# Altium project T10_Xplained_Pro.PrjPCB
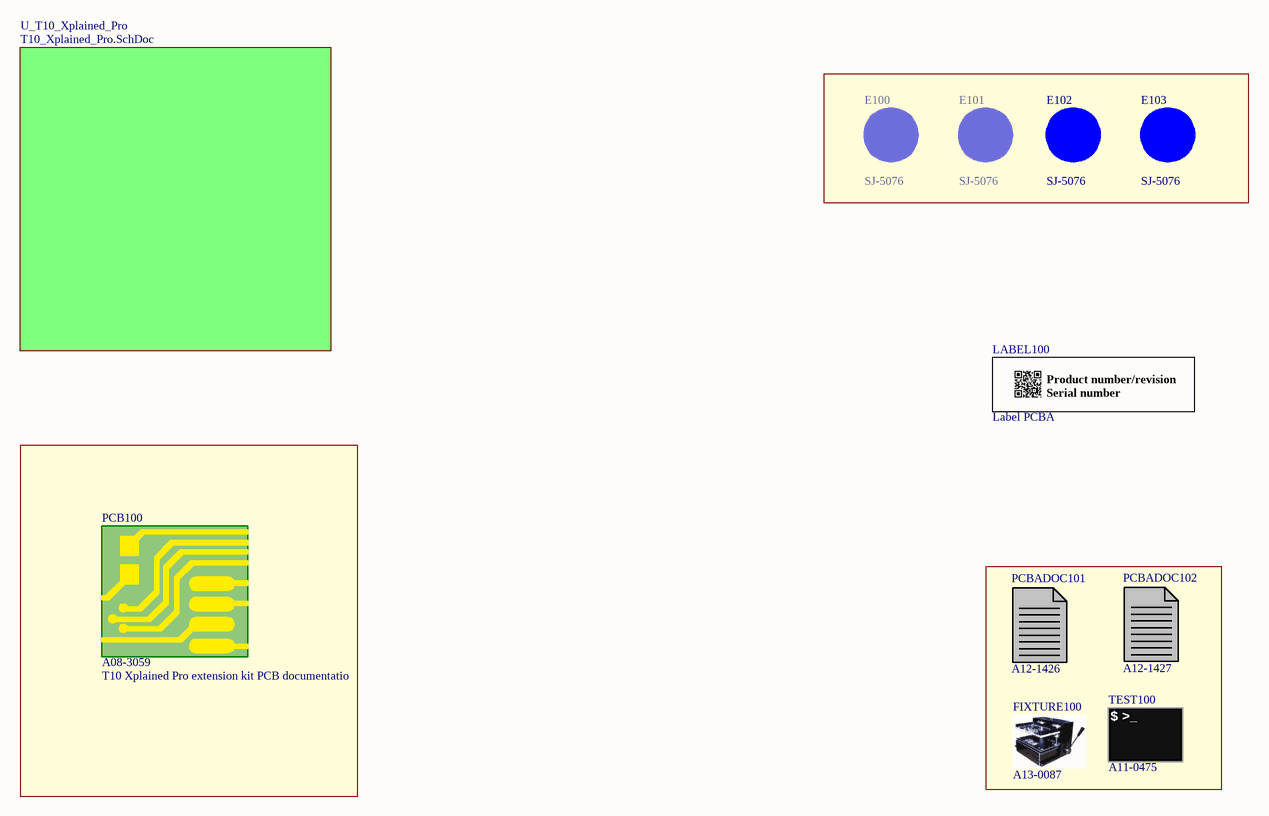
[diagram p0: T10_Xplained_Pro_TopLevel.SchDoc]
2 sheets, 68 parts. Net scope: global (net labels, ports and power ports of the same name join across sheets).
Board file: T10_Xplained_Pro.PcbDoc
Sheets:
  T10_Xplained_Pro_TopLevel.SchDoc
    U_T10_Xplained_Pro = T10_Xplained_Pro.SchDoc

## Sheet T10_Xplained_Pro_TopLevel.SchDoc: Top Level
size A3; Organization: ATMEL Norway; Address1: Vestre Rosten 79; Address2: N-7075 TILLER; Address3: NORWAY; DocumentNumber: A09-3338; Revision: 1; SheetNumber: 1; SheetTotal: 2; DrawnBy: Sivaram SL; Engineer: Sivaram SL; PageSetup: Record=PageOptions¦CenterHorizontal=True¦CenterVertical=True¦PrintScale=1.01¦XCorrection=1.00¦YCorrection=1.00¦PrintKind=1¦BorderSize=5000000¦LeftOffset=0¦BottomOffset=0¦Orientation=2¦PaperLength=1000¦PaperWidth=1000¦Scale=100¦PaperSource=7¦PrintQuality=-4¦MediaType=1¦DitherType=10¦PaperKind=Letter¦PrintScaleMode=1

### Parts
?  (no value)  (graphical)
E100  value SJ-5076  [AP8-00192]
E101  value SJ-5076  [AP8-00192]
E102  value SJ-5076  [AP8-00192]
E103  value SJ-5076  [AP8-00192]
FIXTURE100  AN: A13-0087  (hidden comment: JIG)  (mechanical)
LABEL100  value Label PCBA  [AP8-00317]
PCB100  value T10 Xplained Pro extension kit PCB documentatio  AN: A08-3059  (hidden comment: PCB)  (mechanical)
PCBADOC101  AN: A12-1426  (hidden comment: PCBADOC)  (mechanical)
PCBADOC102  AN: A12-1427  (hidden comment: PCBADOC)  (mechanical)
TEST100  AN: A11-0475  (hidden comment: TEST)  (mechanical)

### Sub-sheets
U_T10_Xplained_Pro = T10_Xplained_Pro.SchDoc: no entries

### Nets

Not connected (* = marked no-connect by the designer): E100 1(FIDUCIAL); E101 1(FIDUCIAL); E102 1(FIDUCIAL); E103 1(FIDUCIAL)

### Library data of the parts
? = Title Block A3
E100-E103 = A08-0053: 2.8mm adhesive feet,diam 8.0mm; PartGroup: Mechanical devices,Mounting accessories; Manufacturer: 3M
FIXTURE100 = A13-0087: Xplained PRO Extension board Jupiter Test Fixture; PartGroup: Test Equipment,Test Fixtures; Manufacturer: ESCATEC
LABEL100 = A09-0611: PCBA identification label PP Top White Gloss; PartGroup: Mechanical devices,Packaging materials,Printed Labels; Manufacturer: ACT Logimark AS; MPN: 505462
PCB100 = A08-3059: T10 Xplained Pro extension kit PCB documentation; PartGroup: Mechanical devices,Printed circuit boards; ComponentStatus: 'Active (verified)'
PCBADOC101 = A12-1426: T10 Xplained Pro extension kit PCBA Documentation; PartGroup: Documentation,PCBA Documents,Atmel; ComponentStatus: 'New (not verified)'
PCBADOC102 = A12-1427: T10 Xplained Pro Test Documentation; PartGroup: Documentation,Procedures,Test Instructions; ComponentStatus: 'New (not verified)'
TEST100 = A11-0475: Fixture eggTest for T10 Xplained Pro; PartGroup: Software,Test software,Starter Kit; Value: T10 Xplained Pro test software; ComponentStatus: 'New (not verified)'

## Sheet T10_Xplained_Pro.SchDoc: T10-Xplained Pro
size A3; Organization: ATMEL Norway; Address1: Vestre Rosten 79; Address2: N-7075 TILLER; Address3: NORWAY; DocumentNumber: A09-3338; Revision: 1; SheetNumber: 2; SheetTotal: 2; DrawnBy: Sivaram SL; Engineer: Sivaram SL; PageSetup: Record=PageOptions¦CenterHorizontal=True¦CenterVertical=True¦PrintScale=1.01¦XCorrection=1.00¦YCorrection=1.00¦PrintKind=1¦BorderSize=5000000¦LeftOffset=0¦BottomOffset=0¦Orientation=2¦PaperLength=1000¦PaperWidth=1000¦Scale=100¦PaperSource=7¦PrintQuality=-4¦MediaType=1¦DitherType=10¦PaperKind=A3 (297 x 420 mm)¦PrintScaleMode=1
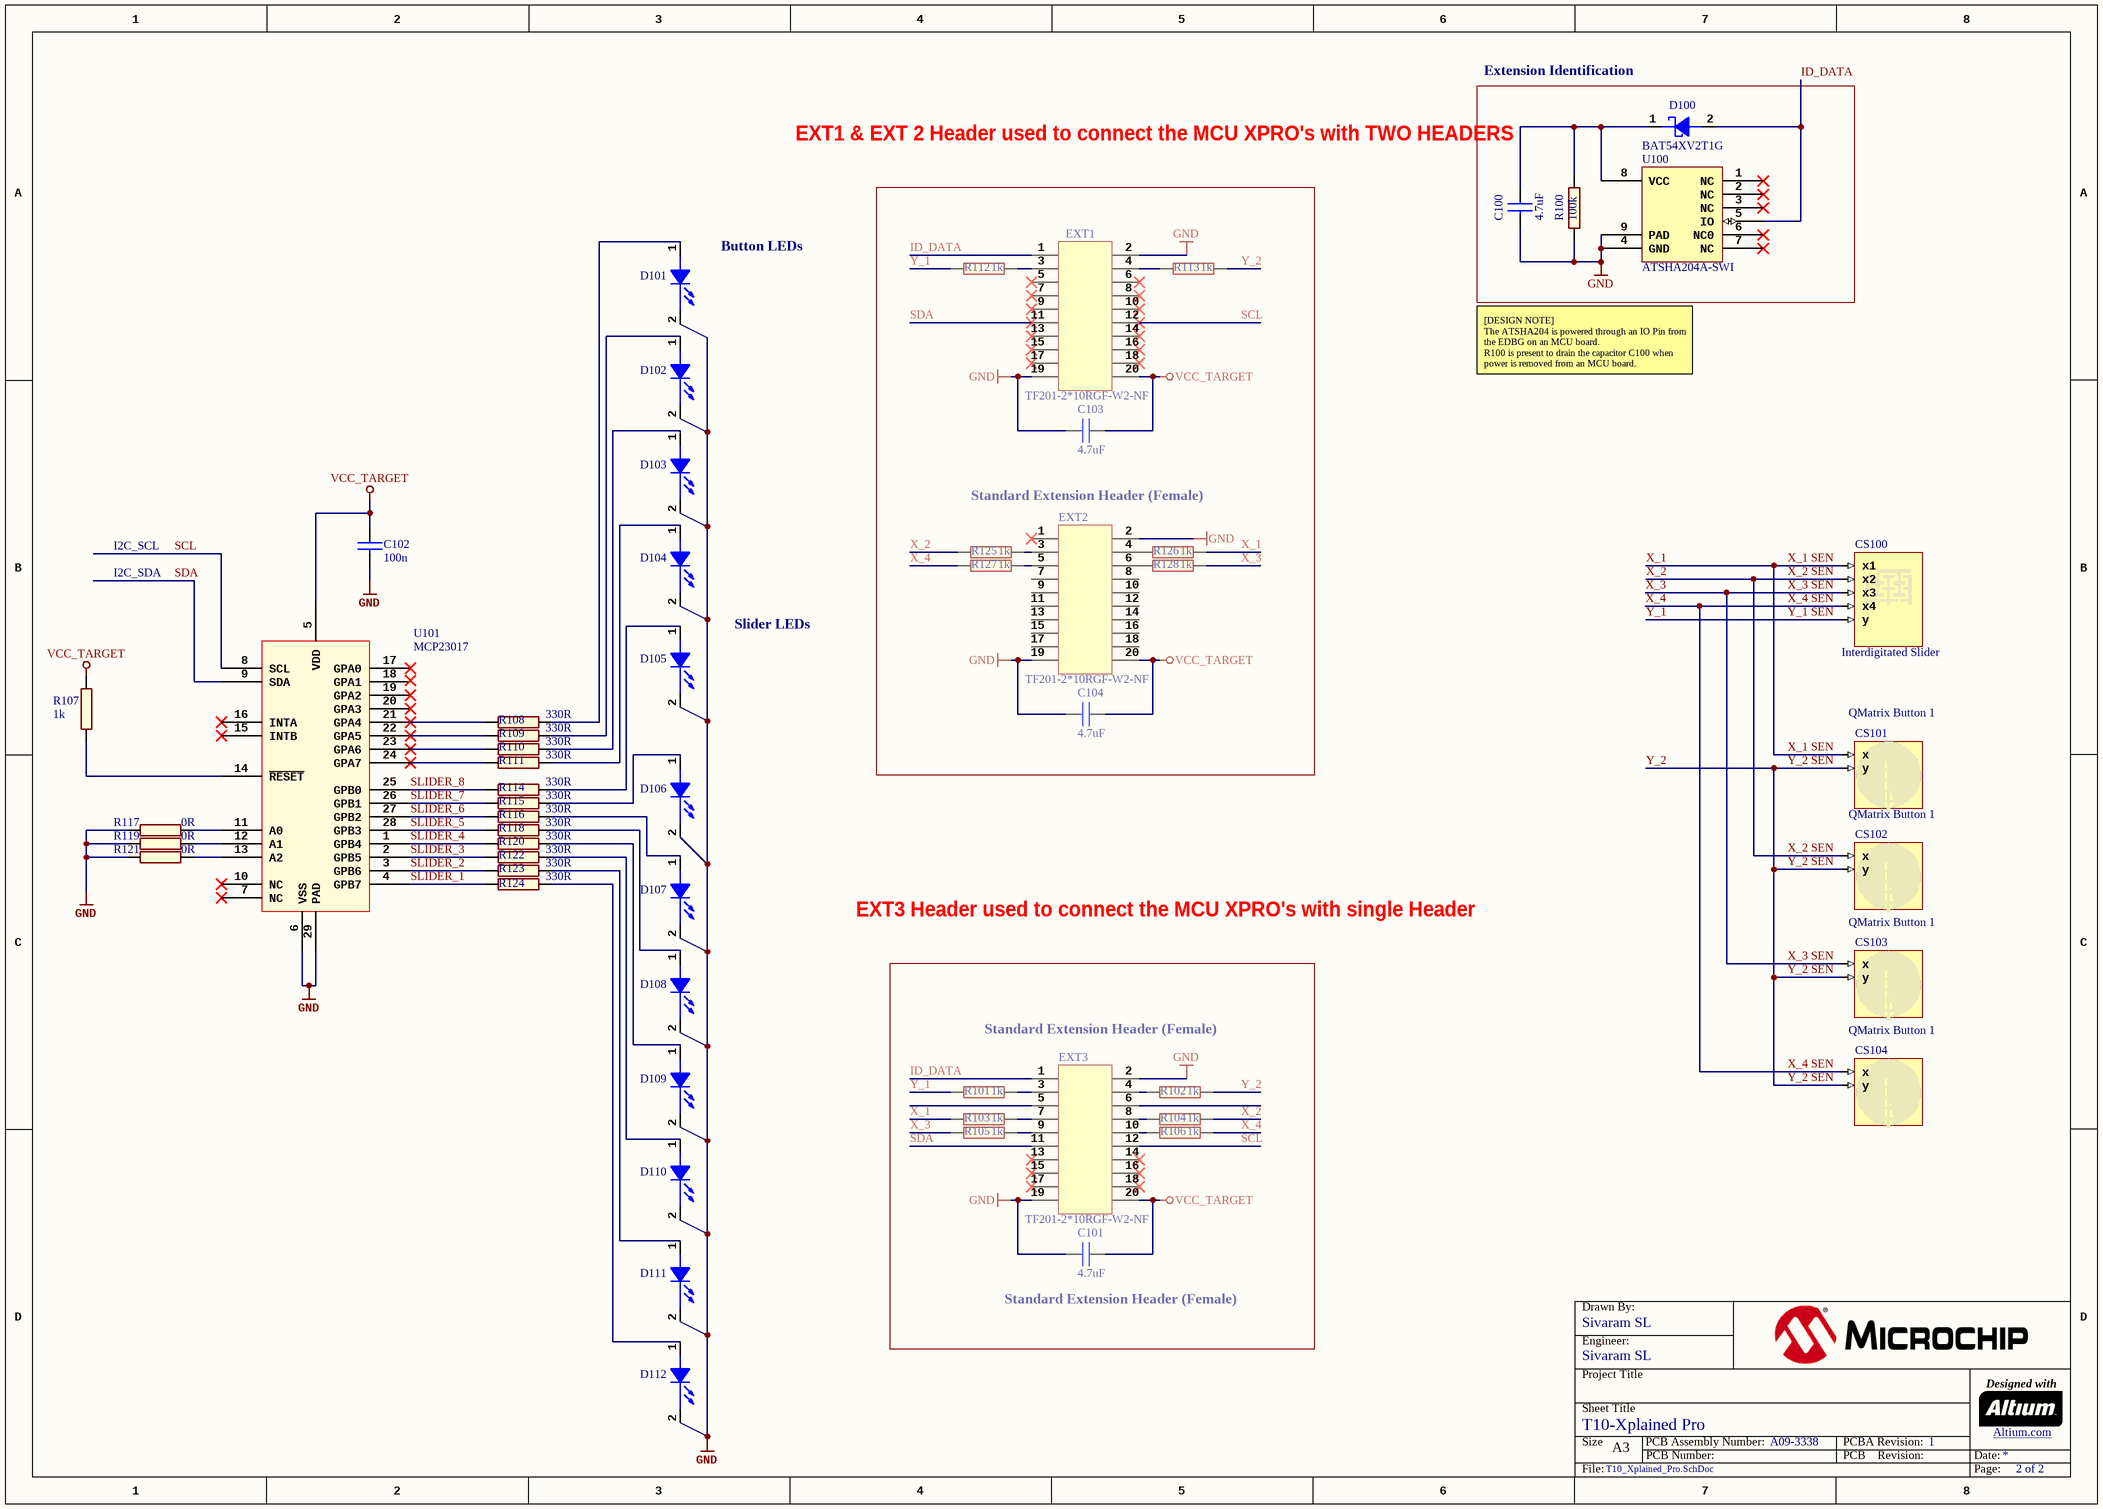
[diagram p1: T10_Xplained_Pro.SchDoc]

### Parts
C100  value 4.7uF  [AP1-00001]  (hidden comment: Recommended by Escatec. No datasheet available yet.)
C101  value 4.7uF  [AP1-00001]
C102  value 100n  [AP1-00053]
C103  value 4.7uF  [AP1-00001]
C104  value 4.7uF  [AP1-00001]
CS100  Interdigitated Slider  (no BOM)
CS101  QMatrix Button 1  (no BOM)
CS102  QMatrix Button 1  (no BOM)
CS103  QMatrix Button 1  (no BOM)
CS104  QMatrix Button 1  (no BOM)
D100  value BAT54XV2T1G  [AP4-00036]  (hidden comment: Farnell# 1615809)
D101  LED_21  [AP4-00115]  (value not drawn)
D102  LED_21  [AP4-00115]  (value not drawn)
D103  LED_21  [AP4-00115]  (value not drawn)
D104  LED_21  [AP4-00115]  (value not drawn)
D105  LED_21  [AP4-00115]  (value not drawn)
D106  LED_21  [AP4-00115]  (value not drawn)
D107  LED_21  [AP4-00115]  (value not drawn)
D108  LED_21  [AP4-00115]  (value not drawn)
D109  LED_21  [AP4-00115]  (value not drawn)
D110  LED_21  [AP4-00115]  (value not drawn)
D111  LED_21  [AP4-00115]  (value not drawn)
D112  LED_21  [AP4-00115]  (value not drawn)
EXT1  value TF201-2*10RGF-W2-NF  [AP8-00621]
EXT2  value TF201-2*10RGF-W2-NF  [AP8-00621]
EXT3  value TF201-2*10RGF-W2-NF  [AP8-00621]
R100  value 100k  [AP2-00000]  (hidden comment: R2)
R101  value 1k  [AP2-00000]  (hidden comment: R2)
R102  value 1k  [AP2-00000]  (hidden comment: R2)
R103  value 1k  [AP2-00000]  (hidden comment: R2)
R104  value 1k  [AP2-00000]  (hidden comment: R2)
R105  value 1k  [AP2-00000]  (hidden comment: R2)
R106  value 1k  [AP2-00000]  (hidden comment: R2)
R107  value 1k  [AP2-00011]
R108  value 330R  [AP2-00000]  (hidden comment: R2)
R109  value 330R  [AP2-00000]  (hidden comment: R2)
R110  value 330R  [AP2-00000]  (hidden comment: R2)
R111  value 330R  [AP2-00000]  (hidden comment: R2)
R112  value 1k  [AP2-00000]  (hidden comment: R2)
R113  value 1k  [AP2-00000]  (hidden comment: R2)
R114  value 330R  [AP2-00000]  (hidden comment: R2)
R115  value 330R  [AP2-00000]  (hidden comment: R2)
R116  value 330R  [AP2-00000]  (hidden comment: R2)
R117  value 0R  [AP2-00000]  (hidden comment: R2)
R118  value 330R  [AP2-00000]  (hidden comment: R2)
R119  value 0R  [AP2-00000]  (hidden comment: R2)
R120  value 330R  [AP2-00000]  (hidden comment: R2)
R121  value 0R  [AP2-00000]  (hidden comment: R2)
R122  value 330R  [AP2-00000]  (hidden comment: R2)
R123  value 330R  [AP2-00000]  (hidden comment: R2)
R124  value 330R  [AP2-00000]  (hidden comment: R2)
R125  value 1k  [AP2-00000]  (hidden comment: R2)
R126  value 1k  [AP2-00000]  (hidden comment: R2)
R127  value 1k  [AP2-00000]  (hidden comment: R2)
R128  value 1k  [AP2-00000]  (hidden comment: R2)
U100  ATSHA204A-SWI  [AP6-00409]
U101  value MCP23017  [AP6-00497]  (hidden comment: MCP23017-E_ML)

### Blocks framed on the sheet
Extension Identification: C100 D100 R100 U100
Standard Extension Header (Female): C103 C104 EXT1 EXT2 R112 R113 R125-R128

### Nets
GND: C100.2 C101.2 C102.2 C103.2 C104.2 D101.2(CATHODE) D102.2(CATHODE) D103.2(CATHODE) D104.2(CATHODE) D105.2(CATHODE) D106.2(CATHODE) D107.2(CATHODE) D108.2(CATHODE) D109.2(CATHODE) D110.2(CATHODE) D111.2(CATHODE) D112.2(CATHODE) EXT1.2 EXT1.19 EXT2.2 EXT2.19 EXT3.2 EXT3.19 R100.1 R117.1 R119.1 R121.1 U100.4(GND) U100.9(PAD) U101.6(VSS) U101.29(PAD)
VCC_TARGET: C101.1 C102.1 C103.1 C104.1 EXT1.20 EXT2.20 EXT3.20 R107.2 U101.5(VDD)
ID_DATA: D100.2(ANODE) EXT1.1 EXT3.1 U100.5(IO)
SCL: EXT1.12 EXT3.12 U101.8(SCL)
SDA: EXT1.11 EXT3.11 U101.9(SDA)
SLIDER_1: R124.1 U101.4(GPB7)
SLIDER_2: R123.1 U101.3(GPB6)
SLIDER_3: R122.1 U101.2(GPB5)
SLIDER_4: R120.1 U101.1(GPB4)
SLIDER_5: R118.1 U101.28(GPB3)
SLIDER_6: R116.1 U101.27(GPB2)
SLIDER_7: R115.1 U101.26(GPB1)
SLIDER_8: R114.1 U101.25(GPB0)
X_1: CS100.x1 CS101.x R103.2 R126.1  [also labelled X_1 SEN]
X_2: CS100.x2 CS102.x R104.1 R125.2  [also labelled X_2 SEN]
X_3: CS100.x3 CS103.x R105.2 R128.1  [also labelled X_3 SEN]
X_4: CS100.x4 CS104.x R106.1 R127.2  [also labelled X_4 SEN]
Y_1: CS100.y R101.2 R112.2  [also labelled Y_1 SEN]
Y_2: CS101.y CS102.y CS103.y CS104.y R102.1 R113.1  [also labelled Y_2 SEN]
NetC100_1: C100.1 D100.1(CATHODE) R100.2 U100.8(VCC)
NetD101_1: D101.1(ANODE) R108.2
NetD102_1: D102.1(ANODE) R109.2
NetD103_1: D103.1(ANODE) R110.2
NetD104_1: D104.1(ANODE) R111.2
NetD105_1: D105.1(ANODE) R114.2
NetD106_1: D106.1(ANODE) R115.2
NetD107_1: D107.1(ANODE) R116.2
NetD108_1: D108.1(ANODE) R118.2
NetD109_1: D109.1(ANODE) R120.2
NetD110_1: D110.1(ANODE) R122.2
NetD111_1: D111.1(ANODE) R123.2
NetD112_1: D112.1(ANODE) R124.2
NetEXT1_3: EXT1.3 R112.1
NetEXT1_4: EXT1.4 R113.2
NetEXT2_3: EXT2.3 R125.1
NetEXT2_4: EXT2.4 R126.2
NetEXT2_5: EXT2.5 R127.1
NetEXT2_6: EXT2.6 R128.2
NetEXT3_3: EXT3.3 R101.1
NetEXT3_4: EXT3.4 R102.2
NetEXT3_7: EXT3.7 R103.1
NetEXT3_8: EXT3.8 R104.2
NetEXT3_9: EXT3.9 R105.1
NetEXT3_10: EXT3.10 R106.2
NetR107_1: R107.1 U101.14(~{RESET})
NetR108_1: R108.1 U101.21(GPA4)
NetR109_1: R109.1 U101.22(GPA5)
NetR110_1: R110.1 U101.23(GPA6)
NetR111_1: R111.1 U101.24(GPA7)
NetR117_2: R117.2 U101.11(A0)
NetR119_2: R119.2 U101.12(A1)
NetR121_2: R121.2 U101.13(A2)

Not connected (* = marked no-connect by the designer): EXT1 5* 6* 7* 8* 9* 10* 13* 14* 15* 16* 17* 18*; EXT2 1* 7 8 9 10 11 12 13 14 15 16 17 18; EXT3 5 6 13* 14* 15* 16* 17* 18*; U100 1(NC)* 2(NC)* 3(NC)* 6(NC0)* 7(NC)*; U101 7(NC)* 10(NC)* 15(INTB)* 16(INTA)* 17(GPA0)* 18(GPA1) 19(GPA2)* 20(GPA3)*

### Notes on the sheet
- EXT1 & EXT 2 Header used to connect the MCU XPRO's with TWO HEADERS
- (near D101) Button LEDs
- [DESIGN NOTE]
  The ATSHA204 is powered through an IO Pin from the EDBG on an MCU board.
  R100 is present to drain the capacitor C100 when power is removed from an MCU board.
- I2C_SCL
- I2C_SDA
- Slider LEDs
- EXT3 Header used to connect the MCU XPRO's with single Header
- Standard Extension Header (Female)
- (near C101) Standard Extension Header (Female)

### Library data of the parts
C100 = A01-0347: Ceramic capacitor, SMD 0402, X5R, 6.3V, +/-20% (de33687); PartGroup: Capacitors,Ceramic,SMD 0402; Manufacturer: Murata; MPN: GRM155R60J475ME87D; Tolerance: +-20%; TemperatureRange: -55°C to +85°C; ComponentStatus: 'Active (verified)'
C101 C103 C104 = A01-0347: Ceramic capacitor, SMD 0402, X5R, 6.3V, +/-20% (de33687); PartGroup: Capacitors,Ceramic,SMD 0402; Manufacturer: Murata; MPN: GRM155R60J475ME87D; Tolerance: +-20%; TemperatureRange: -55°C to +85°C
C102 = A01-0246: Ceramic capacitor, SMD 0402, X7R, 16V, +/-10%; PartGroup: Capacitors,Ceramic,SMD 0402; Manufacturer: Kemet; MPN: C0402C104K4RACTU; TemperatureRange: -55 - +125 deg C; ComponentStatus: 'Active (verified)'
CS100 = InterdigitatedSlider: Interdigitated Matrix Slider; ConfiguratorName: ATMEL_TOUCH; ConfigurationParameters: {}__sensorid[10]{}segmentWidth[12]{}height[10]{}yThickness[0.5]{}xThickness[0.5]{}gapThickness[0.5]{}channels[4]{}
CS101-CS104 = QMatrixButton: QMatrix Button; ConfiguratorName: ATMEL_TOUCH; ConfigurationParameters: {}__sensorid[3]{}width[10]{}height[10]{}yThickness[0.5]{}xThickness[0.5]{}gapThickness[0.5]{}path[1]{}
D100 = A04-0049: Schottky diode, If:200mA, Vf:0.35V, Vrrm:30V, SOD-523; PartGroup: Diodes,Schottky; Manufacturer: ON Semiconductor; TemperatureRange: -55°C to +125°C; ComponentStatus: 'Active (verified)'
D101-D112 = A10-0204: LED, SMD, RED, 3.2x1.2mm, reverse mount; Value: LTST-C250KRKT
EXT1-EXT3 = A08-1512: 2x10, female pin header receptable, right-angled, 2.54mm pitch, THM, Pin In Paste; PartGroup: Mechanical devices,Connectors,Pin header receptacle; MPN: F201-2*10RGF-W2-NF; Manufacturer: Pro-data International Corp
R100 = A02-0260: Thick film resistor, SMD 0402, 1/16W, 1%; PartGroup: Resistors,SMD,0402 1%; TemperatureRange: -55 - +125 deg C; ComponentStatus: 'Active (verified)'
R101-R107 R112 R113 R125-R128 = A02-0212: Thick film resistor, SMD 0402, 1/16W, 1%; PartGroup: Resistors,SMD,0402 1%; TemperatureRange: -55 - +125 deg C; ComponentStatus: 'Active (verified)'
R108-R111 R114-R116 R118 R120 R122-R124 = A02-0200: Thick film resistor, SMD 0402, 1/16W, 1%; PartGroup: Resistors,SMD,0402 1%; Manufacturer: ASJ; MPN: CR10-3300-FK; TemperatureRange: -55 - +125 deg C; ComponentStatus: 'Active (verified)'
R117 R119 R121 = A02-0163: RES 0.0 OHM 1/16W 0402 SMD; PartGroup: Resistors,SMD,0402 1%; Manufacturer: (n/a); MPN: RMCF0402ZT0R00; Tolerance: 1 %; TemperatureRange: -55 - +125 deg C; ComponentStatus: 'Active (verified)'
U100 = A06-1276: ATSHA204 with 1-wire interface and UDFN8 package; PartGroup: Integrated Circuits,Special function,Encryption; Manufacturer: ATMEL; MPN: ATSHA204A-MAHCZ-T; Value: ATSHA204 SWI UDFN8; ComponentStatus: 'New (not verified)'
U101 = A06-1534: 16-Bit I/O Expander with I2C interface, 28-Lead QFN; PartGroup: Integrated Circuits,General linear; Manufacturer: Microchip Technology Inc; MPN: MCP23017-E/ML; TemperatureRange: -40Â°C to +125Â°C; ComponentStatus: 'Active (verified)'

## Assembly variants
Default_assembly: not fitted R100
ID powered through VTG: not fitted D100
